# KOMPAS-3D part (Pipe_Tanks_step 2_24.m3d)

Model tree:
1. X Axis
2. Y Axis
3. Z Axis  (labels: Pipe Dn 50)
     Òîëùèíà ñòåíêè 1 = 1

Referenced files in C:\Documents and Settings\kashirsky\Мои документы\Camtasia Studio\Pipelines3D\Tanks\: Tanks_step 2.a3d
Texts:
  Pipe Dn 50
  Steel ASTM A295
  Three Point Plane
  Plane at Angle
  Line and Point Plane
  Axis through Two Vertices
  Axis of Feature
  Axis of Conical Surface
  Axis through Edge
  Trim by Surface
  Trim by Sketch
  Feature with No History
  Intersection Axis of Two Planes
  Two Line Plane
  Line and Face Plane
  Bend by line
  Hole in sheet body
  Cut in sheet body
  Point in CM
  Linear Dimension from Line to Point
  Surface Finish Symbol
  Geometric Tolerance Symbol
  Leader #1
  Leader #2
  Leader #3
  Shape Deviations and Datum
  Node point number
  Mark of coordination axis
  Node point designation
  Mark/Reference designation with leader
  Mark/reference designation on line
  Mark/Reference designation without leader
  Plane of section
